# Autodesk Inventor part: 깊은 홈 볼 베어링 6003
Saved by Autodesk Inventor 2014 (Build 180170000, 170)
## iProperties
Created: 2026-06
Part Number: 깊은 홈 볼 베어링 6003
Material: 일반
Document SubType Name: Modeling
Designer: dg
Density: 1 g/cm^3
Appearance: 기본값
Author: dg
Author: jhkim
Description: 깊은 그루브 볼 베어링
Creation Date: 2026-05-29
Sending System: Autodesk Inventor 2027
Preprocessor: ST-DEVELOPER v20.1
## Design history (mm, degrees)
node "깊은 홈 볼 베어링 60031"
body "Solid1"
node "Solid1_1"
node "Solid1_2"
node "Solid1_3"
node "Solid1_4"
node "Solid1_5"
node "Solid1_6"
node "Solid1_7"
node "Solid1_8"
node "Solid1_9"
node "Solid1_10"
node "기준1"
node "기준2"
node "기준3"
node "기준4"
node "기준5"
node "기준6"
node "기준7"
node "기준8"
node "기준9"
node "기준10"
node "기준11"
